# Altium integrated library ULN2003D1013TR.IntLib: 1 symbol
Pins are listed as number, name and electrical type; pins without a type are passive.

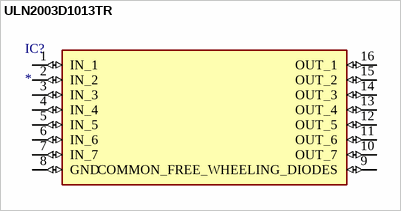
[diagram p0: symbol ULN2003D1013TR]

## ULN2003D1013TR
designator IC?
Bipolar (BJT) Transistor Array 7 NPN Darlington 50V 500mA - - Surface Mount 16-SO; MF: STMicroelectronics; MP: ULN2003D1013TR
footprint SOIC127P600X175-16N
pins: 1 IN_1 (io), 2 IN_2 (io), 3 IN_3 (io), 4 IN_4 (io), 5 IN_5 (io), 6 IN_6 (io), 7 IN_7 (io), 8 GND (io), 9 COMMON_FREE_WHEELING_DIODES (io), 10 OUT_7 (io), 11 OUT_6 (io), 12 OUT_5 (io), 13 OUT_4 (io), 14 OUT_3 (io), 15 OUT_2 (io), 16 OUT_1 (io)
